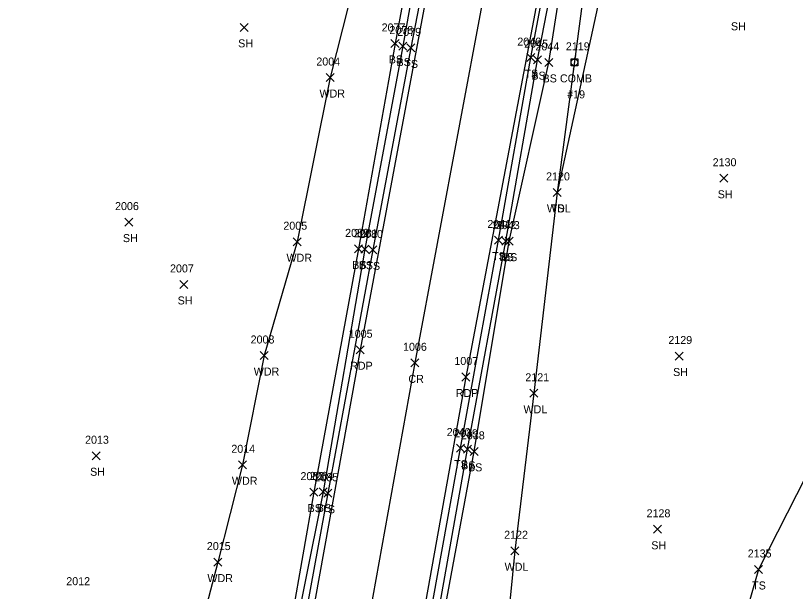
# Model space of a CAD drawing. Extents: x 1754529 to 1755810, y 621660 to 624656.
# Drawn here: x 1755421.2 to 1755616, y 623923.4 to 624067.2 of the extents above; entities that cross this region are included whole.
import ezdxf

# ---------------------------------------------------------------- set-up
doc = ezdxf.new("R2010")
doc.units = 0
for name, color, linetype in [('L_A', 7, 'Continuous'), ('L_I', 7, 'Continuous'), ('L_TIC', 7, 'Continuous'), ('LAWA', 7, 'Continuous'), ('LELB', 7, 'Continuous'), ('Level 14', 7, 'Continuous'), ('P_A', 7, 'Continuous'), ('P_I', 7, 'Continuous'), ('PET', 7, 'Continuous'), ('PRC', 7, 'Continuous'), ('U_A', 7, 'Continuous'), ('U_C', 7, 'Continuous'), ('U_I', 7, 'Continuous'), ('UP', 7, 'Continuous')]:
    doc.layers.add(name, color=color, linetype=linetype)

msp = doc.modelspace()

# ---------------------------------------------------------------- linework, layer by layer
at = {"layer": 'L_TIC'}
for points in [[(1755477.3, 624063.24), (1755479.3, 624065.24)], [(1755479.3, 624063.24), (1755477.3, 624065.24)], [(1755514.97, 624059.22), (1755516.97, 624061.22)], [(1755516.97, 624059.22), (1755514.97, 624061.22)], [(1755516.91, 624058.57), (1755518.91, 624060.57)], [(1755518.91, 624058.57), (1755516.91, 624060.57)], [(1755518.9, 624058.12), (1755520.9, 624060.12)], [(1755520.9, 624058.12), (1755518.9, 624060.12)], [(1755548.93, 624055.68), (1755550.93, 624057.68)], [(1755550.93, 624055.68), (1755548.93, 624057.68)], [(1755550.62, 624055.17), (1755552.62, 624057.17)], [(1755552.62, 624055.17), (1755550.62, 624057.17)], [(1755553.4, 624054.49), (1755555.4, 624056.49)], [(1755555.4, 624054.49), (1755553.4, 624056.49)], [(1755498.73, 624050.71), (1755500.73, 624052.71)], [(1755500.73, 624050.71), (1755498.73, 624052.71)], [(1755597.13, 624025.55), (1755599.13, 624027.55)], [(1755599.13, 624025.55), (1755597.13, 624027.55)], [(1755555.51, 624022.02), (1755557.51, 624024.02)], [(1755557.51, 624022.02), (1755555.51, 624024.02)], [(1755555.51, 624022.02), (1755557.51, 624024.02)], [(1755557.51, 624022.02), (1755555.51, 624024.02)], [(1755448.48, 624014.6), (1755450.48, 624016.6)], [(1755450.48, 624014.6), (1755448.48, 624016.6)], [(1755490.49, 624009.7), (1755492.49, 624011.7)], [(1755492.49, 624009.7), (1755490.49, 624011.7)], [(1755540.82, 624010.12), (1755542.82, 624012.12)], [(1755542.82, 624010.12), (1755540.82, 624012.12)], [(1755542.64, 624009.85), (1755544.64, 624011.85)], [(1755544.64, 624009.85), (1755542.64, 624011.85)], [(1755543.53, 624009.84), (1755545.53, 624011.84)], [(1755545.53, 624009.84), (1755543.53, 624011.84)], [(1755505.84, 624007.91), (1755507.84, 624009.91)], [(1755507.84, 624007.91), (1755505.84, 624009.91)], [(1755507.44, 624007.83), (1755509.44, 624009.83)], [(1755509.44, 624007.83), (1755507.44, 624009.83)], [(1755509.42, 624007.64), (1755511.42, 624009.64)], [(1755511.42, 624007.64), (1755509.42, 624009.64)], [(1755462.17, 623999.03), (1755464.17, 624001.03)], [(1755464.17, 623999.03), (1755462.17, 624001.03)], [(1755482.31, 623981.28), (1755484.31, 623983.28)], [(1755484.31, 623981.28), (1755482.31, 623983.28)], [(1755585.98, 623981.15), (1755587.98, 623983.15)], [(1755587.98, 623981.15), (1755585.98, 623983.15)], [(1755549.67, 623971.84), (1755551.67, 623973.84)], [(1755551.67, 623971.84), (1755549.67, 623973.84)], [(1755531.32, 623958.16), (1755533.32, 623960.16)], [(1755533.32, 623958.16), (1755531.32, 623960.16)], [(1755533.08, 623957.86), (1755535.08, 623959.86)], [(1755535.08, 623957.86), (1755533.08, 623959.86)], [(1755534.77, 623957.34), (1755536.77, 623959.34)], [(1755536.77, 623957.34), (1755534.77, 623959.34)], [(1755440.3, 623956.24), (1755442.3, 623958.24)], [(1755442.3, 623956.24), (1755440.3, 623958.24)], [(1755476.84, 623953.98), (1755478.84, 623955.98)], [(1755478.84, 623953.98), (1755476.84, 623955.98)], [(1755494.69, 623947.15), (1755496.69, 623949.15)], [(1755496.69, 623947.15), (1755494.69, 623949.15)], [(1755497, 623947.21), (1755499, 623949.21)], [(1755499, 623947.21), (1755497, 623949.21)], [(1755498.16, 623946.88), (1755500.16, 623948.88)], [(1755500.16, 623946.88), (1755498.16, 623948.88)], [(1755580.53, 623937.87), (1755582.53, 623939.87)], [(1755582.53, 623937.87), (1755580.53, 623939.87)], [(1755544.94, 623932.51), (1755546.94, 623934.51)], [(1755546.94, 623932.51), (1755544.94, 623934.51)], [(1755470.72, 623929.68), (1755472.72, 623931.68)], [(1755472.72, 623929.68), (1755470.72, 623931.68)], [(1755605.81, 623927.84), (1755607.81, 623929.84)], [(1755607.81, 623927.84), (1755605.81, 623929.84)]]:
    msp.add_lwpolyline(points, dxfattribs=at)
at = {"layer": 'LAWA'}
for points in [[(1755302.36, 624324.44), (1755304.56, 624259.61), (1755306.26, 624221.06), (1755317.77, 624175.11), (1755335.71, 624145.2), (1755381.51, 624131.11), (1755414.09, 624129.63), (1755447.66, 624121.7), (1755477.75, 624119.95), (1755506.85, 624141.45), (1755530.35, 624173.06), (1755521.71, 624132.68), (1755513.72, 624106.64), (1755499.73, 624051.71), (1755491.49, 624010.7), (1755483.31, 623982.28), (1755477.84, 623954.98), (1755471.72, 623930.68), (1755463.31, 623898.52), (1755457.13, 623867.77), (1755453.48, 623847.93), (1755451.28, 623827.38), (1755449.92, 623802.26), (1755447.47, 623775.96)], [(1755611.46, 624290.08), (1755604.25, 624255.82), (1755602.4, 624225.76), (1755589.62, 624209.18), (1755583.3, 624161.08), (1755576.77, 624124.71), (1755568, 624075.88), (1755556.51, 624023.02), (1755550.67, 623972.84), (1755545.94, 623933.51), (1755542.23, 623896.35), (1755539.41, 623871.88), (1755536.68, 623848.06)]]:
    msp.add_lwpolyline(points, dxfattribs=at)
at = {"layer": 'LELB'}
for points in [[(1755564.22, 624305.05), (1755554.36, 624254.73), (1755544.82, 624207.63), (1755534.93, 624160.24), (1755525.26, 624110.43), (1755515.97, 624060.22), (1755506.84, 624008.91), (1755495.69, 623948.15), (1755487.4, 623901.21), (1755479.14, 623855.5), (1755472.16, 623816.92), (1755467.3, 623794.24)], [(1755566.56, 624304.36), (1755555.78, 624254.28), (1755546.32, 624207.47), (1755536.63, 624160.1), (1755526.96, 624110.16), (1755517.91, 624059.57), (1755508.44, 624008.83), (1755498, 623948.21), (1755488.64, 623901.37), (1755480.93, 623855.25), (1755473.47, 623816.7), (1755469.09, 623793.73)], [(1755569.13, 624303.44), (1755557.49, 624253.71), (1755548.32, 624207.42), (1755537.91, 624159.58), (1755529.76, 624109.95), (1755519.9, 624059.12), (1755510.42, 624008.64), (1755499.16, 623947.88), (1755490.5, 623900.71), (1755482.67, 623854.46), (1755475.56, 623816.58), (1755471.08, 623793.12)], [(1755503.59, 623800.12), (1755513.5, 623853.71), (1755523.35, 623909.32), (1755532.32, 623959.16), (1755541.82, 624011.12), (1755549.93, 624056.68), (1755559.84, 624109.07), (1755568.22, 624149.47), (1755576.95, 624193.92), (1755586.25, 624237.06), (1755598.86, 624293.76)], [(1755505.03, 623799.81), (1755514.71, 623853.68), (1755525.28, 623909.17), (1755534.08, 623958.86), (1755543.64, 624010.85), (1755551.62, 624056.17), (1755561.79, 624108.88), (1755569.47, 624149.58), (1755577.75, 624193.77), (1755587.59, 624237.08), (1755601.72, 624293.11)], [(1755506.63, 623799.61), (1755516.45, 623853.4), (1755526.55, 623908.94), (1755535.77, 623958.34), (1755544.53, 624010.84), (1755554.4, 624055.49), (1755562.72, 624108.68), (1755571.46, 624149.1), (1755579.12, 624193.4), (1755588.79, 624236.83), (1755601.72, 624293.11)], [(1755593.11, 624246.9), (1755585.82, 624209), (1755577.23, 624161.97), (1755571.27, 624126.25), (1755563.46, 624075.91), (1755556.51, 624023.02)], [(1755642.06, 624060.86), (1755634.66, 624026.67), (1755623.28, 624004), (1755620.94, 623965.19), (1755618.71, 623952.2), (1755606.81, 623928.84), (1755598.16, 623898.45), (1755598.5, 623876.91), (1755607.67, 623866.57), (1755613.91, 623849.85), (1755612.83, 623834.4)]]:
    msp.add_lwpolyline(points, dxfattribs=at)
at = {"layer": 'Level 14'}
for points in [[(1755506.27, 623982.72), (1755508.27, 623984.72)], [(1755508.27, 623982.72), (1755506.27, 623984.72)], [(1755519.89, 623979.45), (1755521.89, 623981.45)], [(1755521.89, 623979.45), (1755519.89, 623981.45)], [(1755532.66, 623975.91), (1755534.66, 623977.91)], [(1755534.66, 623975.91), (1755532.66, 623977.91)]]:
    msp.add_lwpolyline(points, dxfattribs=at)
at = {"layer": 'PET'}
for points in [[(1755535.07, 624132.59), (1755507.27, 623983.72), (1755476.9, 623815.46), (1755460.3, 623719.87), (1755437.79, 623591.8), (1755421.36, 623504.45), (1755418.26, 623495.73), (1755404.2, 623424.5), (1755397.43, 623386.49), (1755390.98, 623344.71), (1755391.72, 623340.77), (1755385.02, 623296.56), (1755379.33, 623252.08), (1755376.53, 623216.25), (1755375.95, 623174.43), (1755377.19, 623132.58)], [(1755561.91, 624125.77), (1755533.66, 623976.91), (1755504.04, 623811.48), (1755486.8, 623713.65), (1755464.22, 623587.1), (1755446.31, 623490.47), (1755433.28, 623420.6), (1755425.75, 623380.35), (1755417.64, 623332.29), (1755411.38, 623292.51), (1755405.94, 623251.45), (1755403.49, 623215.07), (1755403.14, 623175.05), (1755404.1, 623131.29)]]:
    msp.add_lwpolyline(points, dxfattribs=at)
at = {"layer": 'PRC'}
msp.add_lwpolyline([(1755548.82, 624129.6), (1755520.89, 623980.45), (1755490.93, 623813.93), (1755473.47, 623716.78), (1755450.77, 623588.43), (1755432.8, 623492.49), (1755420.05, 623422.21), (1755412.93, 623383.28), (1755404.64, 623333.82), (1755398.35, 623294.75), (1755393.11, 623251.83), (1755390.3, 623215.98), (1755389.28, 623175.01), (1755390.29, 623132.74)], dxfattribs=at)
at = {"layer": 'UP'}
for p, q in [((1755561.05, 624057.17), (1755560.8, 624056.34)), ((1755559.97, 624054.67), (1755559.97, 624056.34)), ((1755559.97, 624056.34), (1755561.64, 624056.34)), ((1755561.64, 624054.67), (1755559.97, 624054.67)), ((1755560.55, 624053.84), (1755560.8, 624054.67)), ((1755560.8, 624055.5), (1755560.8, 624055.5)), ((1755561.64, 624056.34), (1755561.64, 624054.67))]:
    msp.add_line(p, q, dxfattribs=at)
msp.add_circle((1755560.8, 624055.5), 0.833, dxfattribs=at)

# ---------------------------------------------------------------- texts
at = {"layer": 'L_A'}
for s, p in [('SH', (1755599.92, 624063.51)), ('SH', (1755476.78, 624059.24)), ('BS', (1755514.41, 624055.22)), ('BS', (1755516.35, 624054.57)), ('TS', (1755518.31, 624054.12)), ('TS', (1755548.33, 624051.68)), ('BS', (1755550.06, 624051.17)), ('BS', (1755552.84, 624050.49)), ('WDR', (1755497.09, 624046.71)), ('SH', (1755596.61, 624021.55)), ('WDL', (1755553.93, 624018.02)), ('TS', (1755554.92, 624018.02)), ('SH', (1755447.97, 624010.6)), ('TS', (1755540.23, 624006.12)), ('BS', (1755542.08, 624005.85)), ('BS', (1755542.97, 624005.84)), ('WDR', (1755488.85, 624005.7)), ('BS', (1755505.28, 624003.91)), ('BS', (1755506.88, 624003.83)), ('TS', (1755508.83, 624003.64)), ('SH', (1755461.65, 623995.03)), ('WDR', (1755480.67, 623977.28)), ('SH', (1755585.47, 623977.15)), ('WDL', (1755548.08, 623967.84)), ('TS', (1755530.73, 623954.16)), ('BS', (1755532.52, 623953.86)), ('BS', (1755534.22, 623953.34)), ('SH', (1755439.78, 623952.24)), ('WDR', (1755475.21, 623949.98)), ('BS', (1755494.13, 623943.15)), ('BS', (1755496.44, 623943.21)), ('TS', (1755497.57, 623942.88)), ('SH', (1755580.02, 623933.87)), ('WDL', (1755543.36, 623928.51)), ('WDR', (1755469.09, 623925.68)), ('TS', (1755605.22, 623923.84))]:
    msp.add_text(s, height=2, dxfattribs=at).set_placement(p)
at = {"layer": 'L_I'}
for s, p in [('2077', (1755512.63, 624063.22)), ('2078', (1755514.57, 624062.57)), ('2079', (1755516.55, 624062.12)), ('2046', (1755546.53, 624059.68)), ('2045', (1755548.28, 624059.17)), ('2044', (1755551.06, 624058.49)), ('2004', (1755496.31, 624054.71)), ('2130', (1755595.35, 624029.55)), ('2120', (1755553.73, 624026.02)), ('2120', (1755553.73, 624026.02)), ('2006', (1755446.01, 624018.6)), ('2005', (1755488.07, 624013.7)), ('2041', (1755539.05, 624014.12)), ('2042', (1755540.3, 624013.85)), ('2043', (1755541.19, 624013.84)), ('2082', (1755503.51, 624011.91)), ('2081', (1755505.67, 624011.83)), ('2080', (1755507, 624011.64)), ('2007', (1755459.75, 624003.03)), ('2008', (1755479.89, 623985.28)), ('2129', (1755584.28, 623985.15)), ('2121', (1755548.54, 623975.84)), ('2040', (1755528.9, 623962.16)), ('2039', (1755530.74, 623961.86)), ('2038', (1755532.44, 623961.34)), ('2013', (1755438.52, 623960.24)), ('2014', (1755475.07, 623957.98)), ('2084', (1755494.66, 623951.21)), ('2083', (1755492.35, 623951.15)), ('2085', (1755495.83, 623950.88)), ('2128', (1755578.84, 623941.87)), ('2122', (1755543.25, 623936.51)), ('2015', (1755468.95, 623933.68)), ('2135', (1755604.12, 623931.84)), ('2012', (1755433.82, 623924.91))]:
    msp.add_text(s, height=2, dxfattribs=at).set_placement(p)
at = {"layer": 'P_A'}
for s, p in [('RDP', (1755504.76, 623978.72)), ('CR', (1755519.32, 623975.45)), ('RDP', (1755531.15, 623971.91))]:
    msp.add_text(s, height=2, dxfattribs=at).set_placement(p)
at = {"layer": 'P_I'}
for s, p in [('1005', (1755504.42, 623986.72)), ('1006', (1755517.98, 623983.45)), ('1007', (1755530.81, 623979.91))]:
    msp.add_text(s, height=2, dxfattribs=at).set_placement(p)
at = {"layer": 'U_A'}
msp.add_text('COMB', height=2, dxfattribs=at).set_placement((1755557.19, 624050.5))
at = {"layer": 'U_C'}
msp.add_text('#19', height=2, dxfattribs=at).set_placement((1755559, 624046.5))
at = {"layer": 'U_I'}
msp.add_text('2119', height=2, dxfattribs=at).set_placement((1755558.67, 624058.5))

doc.saveas('drawing.dxf')
